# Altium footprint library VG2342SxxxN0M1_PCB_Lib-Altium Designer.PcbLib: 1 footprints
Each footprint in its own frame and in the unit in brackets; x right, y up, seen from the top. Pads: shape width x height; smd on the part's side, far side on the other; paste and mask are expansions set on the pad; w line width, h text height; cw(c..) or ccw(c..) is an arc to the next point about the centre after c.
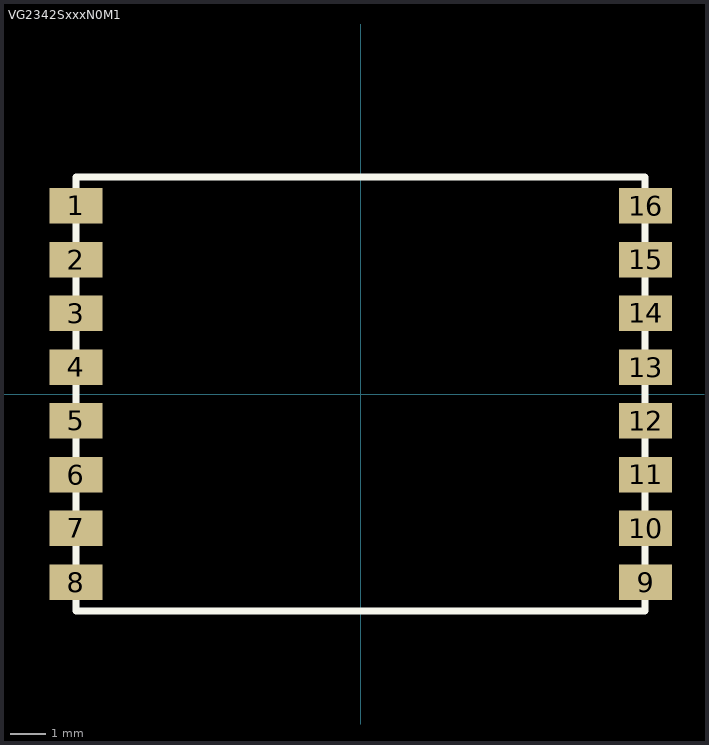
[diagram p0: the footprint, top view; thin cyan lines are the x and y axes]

## VG2342SxxxN0M1 [mm]
pads (17):
  round 1 on Top Overlay: 1(-8.636,6.731)
  rect 1.5x1 smd: 1(-8.007,5.29) 2(-8.007,3.778) 3(-8.007,2.267) 4(-8.007,0.756) 5(-8.007,-0.756) 6(-8.007,-2.267) 7(-8.007,-3.778) 8(-8.007,-5.29) 9(8.007,-5.29) 10(8.007,-3.778) 11(8.007,-2.267) 12(8.007,-0.756) 13(8.007,0.756) 14(8.007,2.267) 15(8.007,3.778) 16(8.007,5.29)
Top Overlay:
  lines w0.2: -8.007,-6.104 7.995,-6.104 7.995,6.104 -8.007,6.104 -8.007,-6.104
